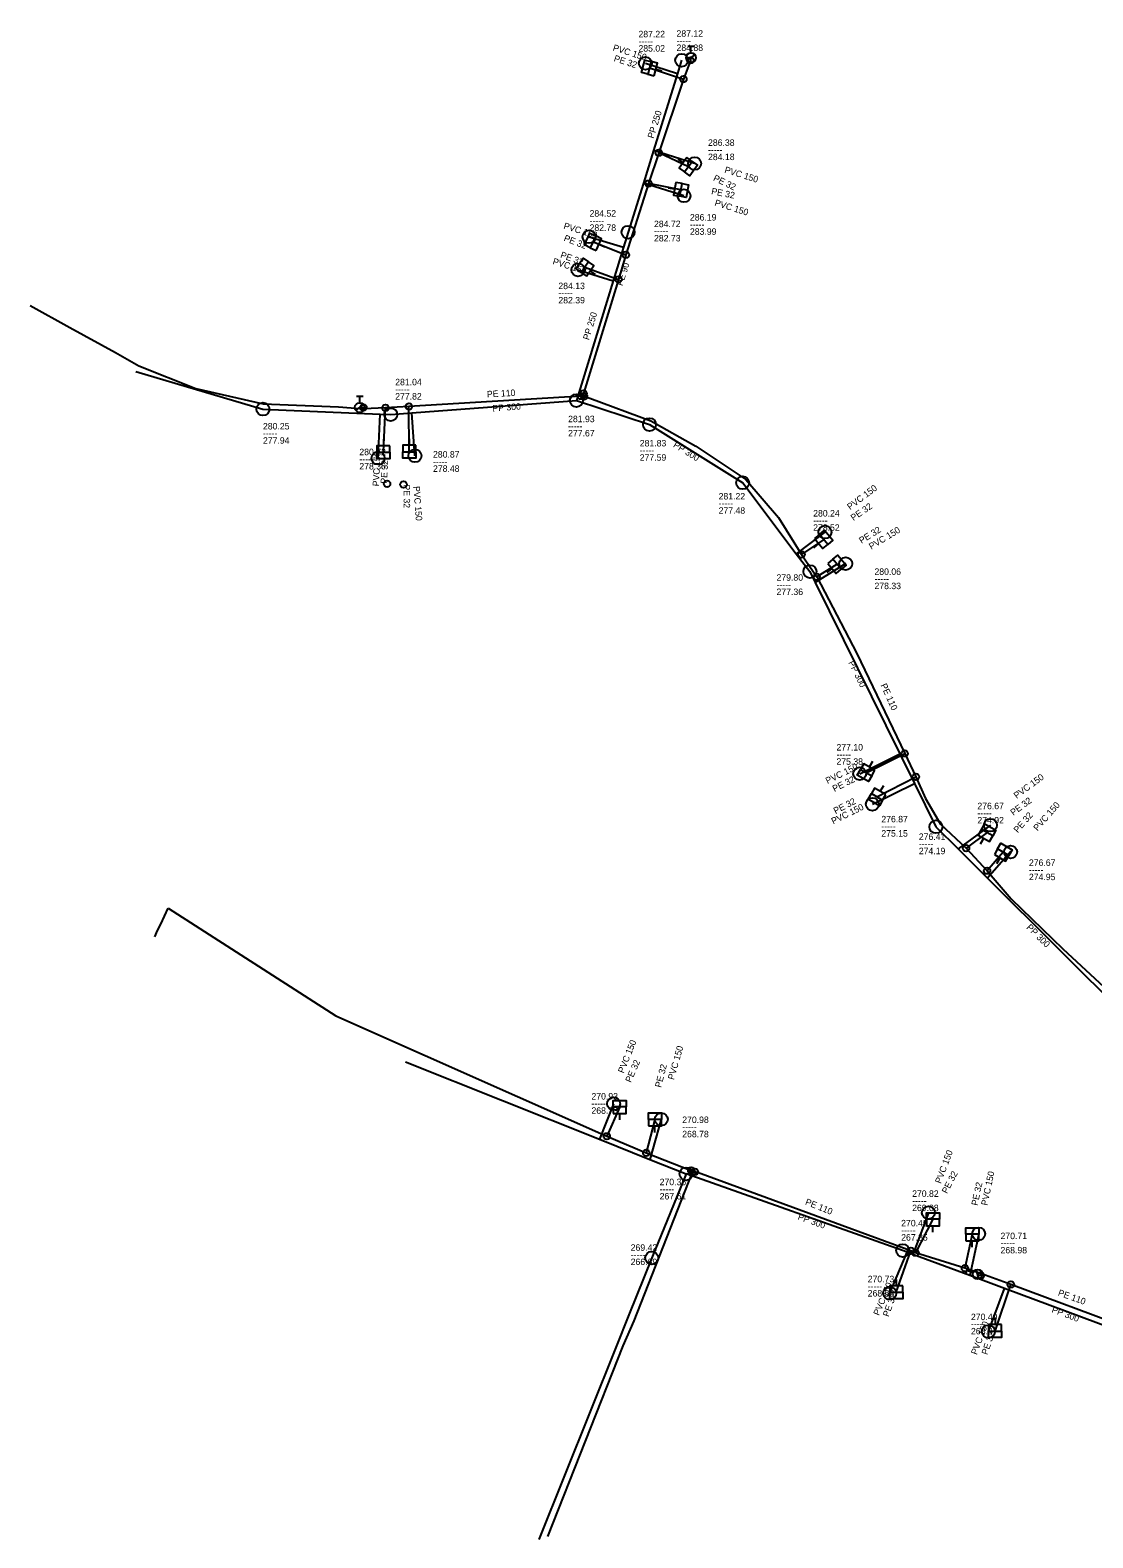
# Model space of a CAD drawing. Extents: x -770828 to -770111, y -1050344 to -1049447.
# Drawn here: x -770783 to -770619.1, y -1049725.3 to -1049492.8 of the extents above; entities that cross this region are included whole.
import ezdxf

# ---------------------------------------------------------------- set-up
doc = ezdxf.new("R2010")
doc.units = 0
doc.layers.add('Level 0', color=7, linetype='Continuous')

msp = doc.modelspace()

# ---------------------------------------------------------------- linework, layer by layer
at = {"layer": 'Level 0'}
for p, q in [((-770682.49, -1049497.41), (-770683.12, -1049499.43)), ((-770681.14, -1049497.42), (-770682.22, -1049500.31)), ((-770681.64, -1049497.47), (-770680.46, -1049496.55)), ((-770681.55, -1049495.26), (-770680.55, -1049495.26)), ((-770681.05, -1049497.01), (-770681.14, -1049497.42)), ((-770681.05, -1049496.26), (-770681.05, -1049495.26)), ((-770688.08, -1049497.88), (-770683.12, -1049499.43)), ((-770687.46, -1049498.59), (-770682.22, -1049500.31)), ((-770683.12, -1049499.43), (-770686.83, -1049511.35)), ((-770685.53, -1049499.11), (-770686.49, -1049498.85)), ((-770682.22, -1049500.31), (-770686.01, -1049511.67)), ((-770686.83, -1049511.35), (-770688.39, -1049516.36)), ((-770680.49, -1049513.33), (-770686.83, -1049511.35)), ((-770686.01, -1049511.67), (-770687.6, -1049516.43)), ((-770681.45, -1049513.82), (-770686.01, -1049511.67)), ((-770683.07, -1049512.64), (-770682.26, -1049513.23)), ((-770687.6, -1049516.43), (-770691.1, -1049527.4)), ((-770688.39, -1049516.36), (-770690.75, -1049523.93)), ((-770682.13, -1049518.31), (-770688.39, -1049516.36)), ((-770682.6, -1049517.41), (-770687.6, -1049516.43)), ((-770684.57, -1049517.06), (-770683.58, -1049517.24)), ((-770696.76, -1049524.63), (-770691.46, -1049526.25)), ((-770690.75, -1049523.93), (-770691.46, -1049526.25)), ((-770696.16, -1049525.41), (-770691.1, -1049527.4)), ((-770694.35, -1049526.26), (-770695.25, -1049525.83)), ((-770691.46, -1049526.25), (-770693.04, -1049531.41)), ((-770691.1, -1049527.4), (-770692.22, -1049531.2)), ((-770698.48, -1049529.74), (-770693.04, -1049531.41)), ((-770697.41, -1049529.3), (-770692.22, -1049531.2)), ((-770695.77, -1049530.45), (-770696.59, -1049529.87)), ((-770693.04, -1049531.41), (-770698.71, -1049549.9)), ((-770692.22, -1049531.2), (-770697.62, -1049548.8)), ((-770782.95, -1049535.22), (-770776.82, -1049538.65)), ((-770776.82, -1049538.65), (-770769.8, -1049542.5)), ((-770769.8, -1049542.5), (-770766.19, -1049544.55)), ((-770766.66, -1049545.41), (-770747.05, -1049551.21)), ((-770766.19, -1049544.55), (-770757.41, -1049548.05)), ((-770757.41, -1049548.05), (-770747, -1049550.4)), ((-770747, -1049550.4), (-770735.4, -1049550.86)), ((-770735.4, -1049550.86), (-770731.52, -1049551.16)), ((-770732.71, -1049551.43), (-770731.53, -1049550.51)), ((-770732.62, -1049549.22), (-770731.62, -1049549.22)), ((-770732.12, -1049550.22), (-770732.12, -1049549.22)), ((-770724.54, -1049550.8), (-770728.16, -1049551)), ((-770697.98, -1049549.2), (-770724.54, -1049550.8)), ((-770724.5, -1049557.78), (-770724.54, -1049550.8)), ((-770724.12, -1049551.81), (-770698.71, -1049549.9)), ((-770698.71, -1049549.9), (-770687.45, -1049553.59)), ((-770697.98, -1049549.2), (-770697.75, -1049549.24)), ((-770697.62, -1049548.8), (-770697.75, -1049549.24)), ((-770697.75, -1049549.24), (-770697.54, -1049549.28)), ((-770697.54, -1049549.28), (-770696.66, -1049549.52)), ((-770696.66, -1049549.52), (-770687.25, -1049553.03)), ((-770747.05, -1049551.21), (-770729, -1049551.98)), ((-770732.12, -1049550.97), (-770731.57, -1049550.96)), ((-770731.57, -1049550.96), (-770731.52, -1049551.16)), ((-770728.16, -1049551), (-770731.52, -1049551.16)), ((-770729.29, -1049558.77), (-770729, -1049551.98)), ((-770729, -1049551.98), (-770727.34, -1049552.05)), ((-770728.47, -1049557.87), (-770728.16, -1049551)), ((-770727.34, -1049552.05), (-770724.12, -1049551.81)), ((-770723.62, -1049558.42), (-770724.12, -1049551.81)), ((-770687.25, -1049553.03), (-770680.29, -1049556.91)), ((-770687.45, -1049553.59), (-770673.08, -1049562.58)), ((-770728.47, -1049555.87), (-770728.47, -1049556.87)), ((-770724.5, -1049555.78), (-770724.5, -1049556.78)), ((-770680.29, -1049556.91), (-770672.58, -1049562.08)), ((-770672.58, -1049562.08), (-770667.57, -1049567.91)), ((-770673.08, -1049562.58), (-770664.81, -1049573.51)), ((-770667.57, -1049567.91), (-770664, -1049573.65)), ((-770660.4, -1049570.18), (-770664.81, -1049573.51)), ((-770660.58, -1049571.31), (-770664, -1049573.65)), ((-770664.81, -1049573.51), (-770662.72, -1049576.27)), ((-770664, -1049573.65), (-770661.67, -1049577.07)), ((-770662.11, -1049572.6), (-770661.35, -1049571.95)), ((-770662.72, -1049576.27), (-770661.9, -1049577.94)), ((-770657.18, -1049575.05), (-770661.9, -1049577.94)), ((-770658.52, -1049575.14), (-770661.67, -1049577.07)), ((-770660.05, -1049576.43), (-770659.29, -1049575.78)), ((-770661.9, -1049577.94), (-770648.84, -1049604.38)), ((-770661.67, -1049577.07), (-770655.46, -1049588.9)), ((-770655.46, -1049588.9), (-770648.1, -1049604.31)), ((-770655.04, -1049607.44), (-770648.84, -1049604.38)), ((-770654.05, -1049607.29), (-770648.1, -1049604.31)), ((-770648.84, -1049604.38), (-770646.59, -1049608.95)), ((-770648.1, -1049604.31), (-770646.39, -1049607.92)), ((-770653.05, -1049605.56), (-770653.55, -1049606.42)), ((-770653.08, -1049612.15), (-770646.59, -1049608.95)), ((-770652.37, -1049611.02), (-770646.39, -1049607.92)), ((-770646.59, -1049608.95), (-770643.29, -1049615.63)), ((-770646.39, -1049607.92), (-770644.9, -1049611.25)), ((-770651.37, -1049609.29), (-770651.87, -1049610.15)), ((-770644.9, -1049611.25), (-770642.58, -1049615.22)), ((-770643.29, -1049615.63), (-770639.86, -1049619.04)), ((-770642.58, -1049615.22), (-770638.64, -1049618.92)), ((-770634.88, -1049615.38), (-770639.86, -1049619.04)), ((-770635.39, -1049616.53), (-770638.64, -1049618.92)), ((-770636.39, -1049618.26), (-770635.89, -1049617.4)), ((-770639.86, -1049619.04), (-770635.31, -1049623.57)), ((-770638.64, -1049618.92), (-770635.4, -1049622.41)), ((-770632.9, -1049619.55), (-770635.4, -1049622.41)), ((-770631.77, -1049619.52), (-770635.31, -1049623.57)), ((-770633.9, -1049621.28), (-770633.4, -1049620.42)), ((-770635.4, -1049622.41), (-770631.67, -1049626.72)), ((-770635.31, -1049623.57), (-770611.67, -1049647.11)), ((-770631.67, -1049626.72), (-770623.69, -1049634.47)), ((-770762.8, -1049630.64), (-770761.69, -1049628.2)), ((-770761.69, -1049628.2), (-770735.81, -1049644.79)), ((-770763.71, -1049632.59), (-770763.31, -1049631.65)), ((-770763.31, -1049631.65), (-770762.8, -1049630.64)), ((-770623.69, -1049634.47), (-770616.65, -1049641)), ((-770735.81, -1049644.79), (-770694.04, -1049663.36)), ((-770725.08, -1049651.88), (-770695.17, -1049663.82)), ((-770692.98, -1049658.34), (-770695.17, -1049663.82)), ((-770692.04, -1049658.84), (-770694.04, -1049663.36)), ((-770692.04, -1049660.84), (-770692.04, -1049659.84)), ((-770686.62, -1049660.77), (-770687.94, -1049665.91)), ((-770685.63, -1049660.75), (-770687.4, -1049666.93)), ((-770686.62, -1049662.77), (-770686.62, -1049661.77)), ((-770695.17, -1049663.82), (-770687.4, -1049666.93)), ((-770694.04, -1049663.36), (-770687.94, -1049665.91)), ((-770687.94, -1049665.91), (-770681.01, -1049668.63)), ((-770687.4, -1049666.93), (-770681.81, -1049669.16)), ((-770689.83, -1049691.85), (-770680.87, -1049669.03)), ((-770681.81, -1049669.16), (-770687.11, -1049682.13)), ((-770648.41, -1049680.99), (-770681.81, -1049669.16)), ((-770681.01, -1049668.63), (-770680.77, -1049668.73)), ((-770680.87, -1049669.03), (-770680.77, -1049668.73)), ((-770680.45, -1049668.86), (-770680.77, -1049668.73)), ((-770680.03, -1049668.97), (-770680.45, -1049668.86)), ((-770647.15, -1049681.04), (-770680.03, -1049668.97)), ((-770644.44, -1049675.15), (-770646.84, -1049681.58)), ((-770643.74, -1049676.16), (-770646.43, -1049681.33)), ((-770643.74, -1049678.16), (-770643.74, -1049677.16)), ((-770637.68, -1049678.47), (-770638.8, -1049683.7)), ((-770636.69, -1049678.42), (-770638.07, -1049684.85)), ((-770649.4, -1049687.43), (-770647.15, -1049681.04)), ((-770647.72, -1049681.25), (-770648.41, -1049680.99)), ((-770646.43, -1049681.33), (-770647.15, -1049681.04)), ((-770637.68, -1049680.47), (-770637.68, -1049679.47)), ((-770687.11, -1049682.13), (-770690.62, -1049690.89)), ((-770650.4, -1049687.56), (-770647.72, -1049681.25)), ((-770646.84, -1049681.58), (-770647.72, -1049681.25)), ((-770638.07, -1049684.85), (-770646.84, -1049681.58)), ((-770638.8, -1049683.7), (-770646.43, -1049681.33)), ((-770649.4, -1049685.43), (-770649.4, -1049686.43)), ((-770636.26, -1049684.58), (-770638.8, -1049683.7)), ((-770638.68, -1049684.54), (-770638.33, -1049683.6)), ((-770637.56, -1049684.41), (-770638.5, -1049684.07)), ((-770632.71, -1049686.85), (-770638.07, -1049684.85)), ((-770636.63, -1049685.38), (-770637.09, -1049683.96)), ((-770636.86, -1049684.67), (-770636.33, -1049684.84)), ((-770636.33, -1049684.84), (-770636.26, -1049684.58)), ((-770631.73, -1049686.21), (-770636.26, -1049684.58)), ((-770635.18, -1049693.48), (-770632.71, -1049686.85)), ((-770634.15, -1049693.42), (-770631.73, -1049686.21)), ((-770611.82, -1049694.65), (-770632.71, -1049686.85)), ((-770611.09, -1049693.93), (-770631.73, -1049686.21)), ((-770690.62, -1049690.89), (-770692.65, -1049695.96)), ((-770691.49, -1049695.69), (-770689.83, -1049691.85)), ((-770634.15, -1049691.42), (-770634.15, -1049692.42)), ((-770692.65, -1049695.96), (-770704.51, -1049725.54)), ((-770703.1, -1049725.08), (-770691.49, -1049695.69))]:
    msp.add_line(p, q, dxfattribs=at)
for points in [[(-770687.72, -1049499.56), (-770688.68, -1049499.3), (-770688.17, -1049497.37), (-770687.2, -1049497.62)], [(-770680.86, -1049513.01), (-770680.05, -1049513.6), (-770681.23, -1049515.22), (-770682.04, -1049514.63)], [(-770682.43, -1049516.43), (-770681.44, -1049516.6), (-770681.79, -1049518.57), (-770682.77, -1049518.39)], [(-770696.58, -1049526.32), (-770697.49, -1049525.89), (-770696.64, -1049524.08), (-770695.74, -1049524.5)], [(-770697.98, -1049530.12), (-770698.8, -1049529.55), (-770697.66, -1049527.91), (-770696.84, -1049528.48)], [(-770727.47, -1049557.87), (-770727.47, -1049558.87), (-770729.47, -1049558.87), (-770729.47, -1049557.87)], [(-770723.5, -1049557.78), (-770723.5, -1049558.78), (-770725.5, -1049558.78), (-770725.5, -1049557.78)], [(-770661.22, -1049570.54), (-770660.46, -1049569.9), (-770659.17, -1049571.43), (-770659.94, -1049572.08)], [(-770659.16, -1049574.37), (-770658.4, -1049573.73), (-770657.11, -1049575.26), (-770657.88, -1049575.91)], [(-770653.18, -1049607.79), (-770653.68, -1049608.66), (-770655.42, -1049607.66), (-770654.92, -1049606.79)], [(-770651.5, -1049611.52), (-770652, -1049612.39), (-770653.74, -1049611.39), (-770653.24, -1049610.52)], [(-770636.26, -1049616.03), (-770635.76, -1049615.16), (-770634.02, -1049616.16), (-770634.52, -1049617.03)], [(-770633.77, -1049619.05), (-770633.27, -1049618.18), (-770631.53, -1049619.18), (-770632.03, -1049620.05)], [(-770693.04, -1049658.84), (-770693.04, -1049657.84), (-770691.04, -1049657.84), (-770691.04, -1049658.84)], [(-770687.62, -1049660.77), (-770687.62, -1049659.77), (-770685.62, -1049659.77), (-770685.62, -1049660.77)], [(-770644.74, -1049676.16), (-770644.74, -1049675.16), (-770642.74, -1049675.16), (-770642.74, -1049676.16)], [(-770638.68, -1049678.47), (-770638.68, -1049677.47), (-770636.68, -1049677.47), (-770636.68, -1049678.47)], [(-770648.4, -1049687.43), (-770648.4, -1049688.43), (-770650.4, -1049688.43), (-770650.4, -1049687.43)], [(-770633.15, -1049693.42), (-770633.15, -1049694.42), (-770635.15, -1049694.42), (-770635.15, -1049693.42)]]:
    msp.add_lwpolyline(points, dxfattribs=at)
for points in [[(-770686.75, -1049499.81), (-770686.24, -1049497.88), (-770687.2, -1049497.62), (-770687.72, -1049499.56)], [(-770681.67, -1049512.42), (-770682.85, -1049514.04), (-770682.04, -1049514.63), (-770680.86, -1049513.01)], [(-770683.41, -1049516.25), (-770683.76, -1049518.22), (-770682.77, -1049518.39), (-770682.43, -1049516.43)], [(-770695.68, -1049526.74), (-770694.83, -1049524.93), (-770695.74, -1049524.5), (-770696.58, -1049526.32)], [(-770697.16, -1049530.69), (-770696.02, -1049529.05), (-770696.84, -1049528.48), (-770697.98, -1049530.12)], [(-770727.47, -1049556.87), (-770729.47, -1049556.87), (-770729.47, -1049557.87), (-770727.47, -1049557.87)], [(-770723.5, -1049556.78), (-770725.5, -1049556.78), (-770725.5, -1049557.78), (-770723.5, -1049557.78)], [(-770661.99, -1049571.19), (-770660.7, -1049572.72), (-770659.94, -1049572.08), (-770661.22, -1049570.54)], [(-770659.93, -1049575.02), (-770658.64, -1049576.55), (-770657.88, -1049575.91), (-770659.16, -1049574.37)], [(-770652.68, -1049606.92), (-770654.42, -1049605.92), (-770654.92, -1049606.79), (-770653.18, -1049607.79)], [(-770651, -1049610.65), (-770652.74, -1049609.65), (-770653.24, -1049610.52), (-770651.5, -1049611.52)], [(-770636.76, -1049616.9), (-770635.02, -1049617.9), (-770634.52, -1049617.03), (-770636.26, -1049616.03)], [(-770634.27, -1049619.92), (-770632.53, -1049620.92), (-770632.03, -1049620.05), (-770633.77, -1049619.05)], [(-770693.04, -1049659.84), (-770691.04, -1049659.84), (-770691.04, -1049658.84), (-770693.04, -1049658.84)], [(-770687.62, -1049661.77), (-770685.62, -1049661.77), (-770685.62, -1049660.77), (-770687.62, -1049660.77)], [(-770644.74, -1049677.16), (-770642.74, -1049677.16), (-770642.74, -1049676.16), (-770644.74, -1049676.16)], [(-770638.68, -1049679.47), (-770636.68, -1049679.47), (-770636.68, -1049678.47), (-770638.68, -1049678.47)], [(-770648.4, -1049686.43), (-770650.4, -1049686.43), (-770650.4, -1049687.43), (-770648.4, -1049687.43)], [(-770633.15, -1049692.42), (-770635.15, -1049692.42), (-770635.15, -1049693.42), (-770633.15, -1049693.42)]]:
    msp.add_lwpolyline(points, close=True, dxfattribs=at)
for centre, radius in [((-770688.08, -1049497.88), 1), ((-770682.49, -1049497.41), 1), ((-770681.05, -1049497.01), 0.75), ((-770681.14, -1049497.42), 0.5), ((-770682.22, -1049500.31), 0.5), ((-770686.01, -1049511.67), 0.5), ((-770680.49, -1049513.33), 1), ((-770687.6, -1049516.43), 0.5), ((-770682.13, -1049518.31), 1), ((-770690.75, -1049523.93), 1), ((-770696.76, -1049524.63), 1), ((-770691.1, -1049527.4), 0.5), ((-770698.48, -1049529.74), 1), ((-770692.22, -1049531.2), 0.5), ((-770697.62, -1049548.8), 0.5), ((-770747.05, -1049551.21), 1), ((-770732.12, -1049550.97), 0.75), ((-770731.57, -1049550.96), 0.5), ((-770728.16, -1049551), 0.5), ((-770724.54, -1049550.8), 0.5), ((-770698.71, -1049549.9), 1), ((-770697.98, -1049549.2), 0.5), ((-770697.54, -1049549.28), 0.5), ((-770727.34, -1049552.05), 1), ((-770687.45, -1049553.59), 1), ((-770729.29, -1049558.77), 1), ((-770723.62, -1049558.42), 1), ((-770727.92, -1049562.73), 0.5), ((-770725.38, -1049562.84), 0.5), ((-770673.08, -1049562.58), 1), ((-770660.4, -1049570.18), 1), ((-770664, -1049573.65), 0.5), ((-770657.18, -1049575.05), 1), ((-770662.72, -1049576.27), 1), ((-770661.67, -1049577.07), 0.5), ((-770648.1, -1049604.31), 0.5), ((-770655.04, -1049607.44), 1), ((-770646.39, -1049607.92), 0.5), ((-770653.08, -1049612.15), 1), ((-770643.29, -1049615.63), 1), ((-770634.88, -1049615.38), 1), ((-770638.64, -1049618.92), 0.5), ((-770631.77, -1049619.52), 1), ((-770635.4, -1049622.41), 0.5), ((-770692.98, -1049658.34), 1), ((-770685.63, -1049660.75), 1), ((-770694.04, -1049663.36), 0.5), ((-770687.94, -1049665.91), 0.5), ((-770681.81, -1049669.16), 1), ((-770681.01, -1049668.63), 0.5), ((-770680.87, -1049669.03), 0.5), ((-770680.45, -1049668.86), 0.5), ((-770644.44, -1049675.15), 1), ((-770636.69, -1049678.42), 1), ((-770687.11, -1049682.13), 1), ((-770648.41, -1049680.99), 1), ((-770647.15, -1049681.04), 0.5), ((-770646.43, -1049681.33), 0.5), ((-770638.8, -1049683.7), 0.5), ((-770636.86, -1049684.67), 0.75), ((-770636.33, -1049684.84), 0.5), ((-770631.73, -1049686.21), 0.5), ((-770650.4, -1049687.56), 1), ((-770635.18, -1049693.48), 1)]:
    msp.add_circle(centre, radius, dxfattribs=at)

# ---------------------------------------------------------------- texts
for s, p in [('287.12', (-770683.28, -1049493.78)), ('-----', (-770689.15, -1049494.97)), ('287.22', (-770689.15, -1049493.87)), ('285.02', (-770689.15, -1049496.07)), ('-----', (-770683.28, -1049494.88)), ('284.88', (-770683.28, -1049495.98)), ('-----', (-770678.42, -1049511.71)), ('286.38', (-770678.42, -1049510.61)), ('284.18', (-770678.42, -1049512.81)), ('284.52', (-770696.69, -1049521.53)), ('-----', (-770696.69, -1049522.63)), ('282.78', (-770696.69, -1049523.73)), ('284.72', (-770686.75, -1049523.15)), ('-----', (-770681.21, -1049523.23)), ('286.19', (-770681.21, -1049522.13)), ('-----', (-770686.75, -1049524.25)), ('282.73', (-770686.75, -1049525.35)), ('283.99', (-770681.21, -1049524.33)), ('284.13', (-770701.5, -1049532.71)), ('-----', (-770701.5, -1049533.81)), ('282.39', (-770701.5, -1049534.91)), ('-----', (-770726.66, -1049548.64)), ('281.04', (-770726.66, -1049547.54)), ('277.82', (-770726.66, -1049549.74)), ('281.93', (-770700, -1049553.23)), ('-----', (-770747.05, -1049555.45)), ('280.25', (-770747.05, -1049554.35)), ('277.94', (-770747.05, -1049556.55)), ('-----', (-770700, -1049554.33)), ('277.67', (-770700, -1049555.43)), ('280.72', (-770732.19, -1049558.32)), ('280.87', (-770720.83, -1049558.69)), ('-----', (-770688.95, -1049558.07)), ('281.83', (-770688.95, -1049556.97)), ('-----', (-770732.19, -1049559.42)), ('278.36', (-770732.19, -1049560.52)), ('-----', (-770720.83, -1049559.79)), ('278.48', (-770720.83, -1049560.89)), ('277.59', (-770688.95, -1049559.17)), ('281.22', (-770676.79, -1049565.15)), ('-----', (-770676.79, -1049566.25)), ('277.48', (-770676.79, -1049567.35)), ('280.24', (-770662.21, -1049567.78)), ('-----', (-770662.21, -1049568.88)), ('278.52', (-770662.21, -1049569.98)), ('280.06', (-770652.76, -1049576.78)), ('-----', (-770667.86, -1049578.79)), ('279.80', (-770667.86, -1049577.69)), ('-----', (-770652.76, -1049577.88)), ('278.33', (-770652.76, -1049578.98)), ('277.36', (-770667.86, -1049579.89)), ('277.10', (-770658.62, -1049603.87)), ('-----', (-770658.62, -1049604.97)), ('275.38', (-770658.62, -1049606.07)), ('-----', (-770636.89, -1049614.02)), ('276.67', (-770636.89, -1049612.92)), ('-----', (-770651.7, -1049616.05)), ('276.87', (-770651.7, -1049614.95)), ('274.92', (-770636.89, -1049615.12)), ('275.15', (-770651.7, -1049617.15)), ('-----', (-770645.92, -1049618.76)), ('276.41', (-770645.92, -1049617.66)), ('274.19', (-770645.92, -1049619.86)), ('276.67', (-770628.94, -1049621.66)), ('-----', (-770628.94, -1049622.76)), ('274.95', (-770628.94, -1049623.86)), ('270.93', (-770696.4, -1049657.7)), ('-----', (-770696.4, -1049658.8)), ('268.73', (-770696.4, -1049659.9)), ('-----', (-770682.4, -1049662.42)), ('270.98', (-770682.4, -1049661.32)), ('268.78', (-770682.4, -1049663.52)), ('-----', (-770685.88, -1049672.01)), ('270.36', (-770685.88, -1049670.91)), ('270.82', (-770646.95, -1049672.71)), ('267.61', (-770685.88, -1049673.11)), ('-----', (-770646.95, -1049673.81)), ('269.08', (-770646.95, -1049674.91)), ('270.45', (-770648.64, -1049677.26)), ('-----', (-770648.64, -1049678.36)), ('267.85', (-770648.64, -1049679.46)), ('270.71', (-770633.32, -1049679.23)), ('269.42', (-770690.35, -1049681.03)), ('-----', (-770633.32, -1049680.33)), ('268.98', (-770633.32, -1049681.43)), ('-----', (-770690.35, -1049682.13)), ('266.69', (-770690.35, -1049683.23)), ('270.73', (-770653.8, -1049685.88)), ('-----', (-770653.8, -1049686.98)), ('268.53', (-770653.8, -1049688.08)), ('-----', (-770637.88, -1049692.82)), ('270.49', (-770637.88, -1049691.72)), ('268.37', (-770637.88, -1049693.92))]:
    msp.add_text(s, height=1, dxfattribs=at).set_placement(p)
for s, rotation, p in [('PVC 150', 342.646, (-770693.18, -1049495.89)), ('PE 32', 341.828, (-770693.03, -1049497.52)), ('PP 250', 72.705, (-770686.83, -1049509.54)), ('PE 32', 334.044, (-770677.71, -1049515.91)), ('PVC 150', 342.656, (-770675.97, -1049514.72)), ('PE 32', 348.911, (-770677.98, -1049518.06)), ('PVC 150', 342.698, (-770677.49, -1049519.8)), ('PVC 150', 343.004, (-770700.78, -1049523.37)), ('PE 32', 338.531, (-770700.75, -1049525.22)), ('PE 32', 339.893, (-770701.28, -1049527.82)), ('PVC 150', 342.934, (-770702.46, -1049528.84)), ('PE 90', 72.305, (-770691.62, -1049532.28)), ('PP 250', 72.975, (-770696.78, -1049540.63)), ('PE 110', 3.162, (-770712.49, -1049549.41)), ('PP 300', 4.299, (-770711.63, -1049551.6)), ('PVC 150', 87.554, (-770729.15, -1049563.13)), ('PP 300', 327.97, (-770683.88, -1049556.98)), ('PE 32', 87.416, (-770727.92, -1049562.73)), ('PE 32', 270.328, (-770725.38, -1049562.84)), ('PVC 150', 274.326, (-770723.87, -1049563.13)), ('PVC 150', 37.057, (-770656.51, -1049566.81)), ('PE 32', 34.38, (-770656, -1049568.49)), ('PE 32', 31.496, (-770654.76, -1049572)), ('PVC 150', 31.479, (-770653.24, -1049572.92)), ('PP 300', 296.213, (-770656.82, -1049590.31)), ('PE 110', 294.106, (-770651.84, -1049593.79)), ('PVC 150', 26.269, (-770660, -1049609.05)), ('PE 32', 26.604, (-770658.93, -1049610.28)), ('PVC 150', 36.314, (-770630.83, -1049611.35)), ('PE 32', 27.402, (-770658.76, -1049613.69)), ('PE 32', 36.33, (-770631.34, -1049613.96)), ('PVC 150', 26.246, (-770659.11, -1049615.28)), ('PE 32', 48.842, (-770630.66, -1049616.65)), ('PVC 150', 48.844, (-770627.61, -1049616.36)), ('PP 300', 315.126, (-770629.4, -1049631.24)), ('PVC 150', 68.217, (-770691.43, -1049653.72)), ('PVC 150', 74.018, (-770683.69, -1049654.73)), ('PE 32', 66.132, (-770690.32, -1049655.16)), ('PE 32', 75.597, (-770685.66, -1049655.92)), ('PVC 150', 69.532, (-770642.52, -1049670.74)), ('PE 32', 62.512, (-770641.56, -1049672.3)), ('PVC 150', 77.887, (-770635.36, -1049674.11)), ('PE 32', 77.913, (-770636.86, -1049674.12)), ('PE 110', 338.062, (-770663.53, -1049673.86)), ('PP 300', 340.496, (-770664.67, -1049676.18)), ('PVC 150', 66.988, (-770652.06, -1049691.1)), ('PE 32', 70.602, (-770650.57, -1049691.28)), ('PE 110', 340.21, (-770624.54, -1049687.89)), ('PP 300', 339.551, (-770625.52, -1049690.49)), ('PVC 150', 69.567, (-770636.98, -1049697.14)), ('PE 32', 71.446, (-770635.34, -1049697.15))]:
    msp.add_text(s, height=1, rotation=rotation, dxfattribs=at).set_placement(p)

doc.saveas('drawing.dxf')
